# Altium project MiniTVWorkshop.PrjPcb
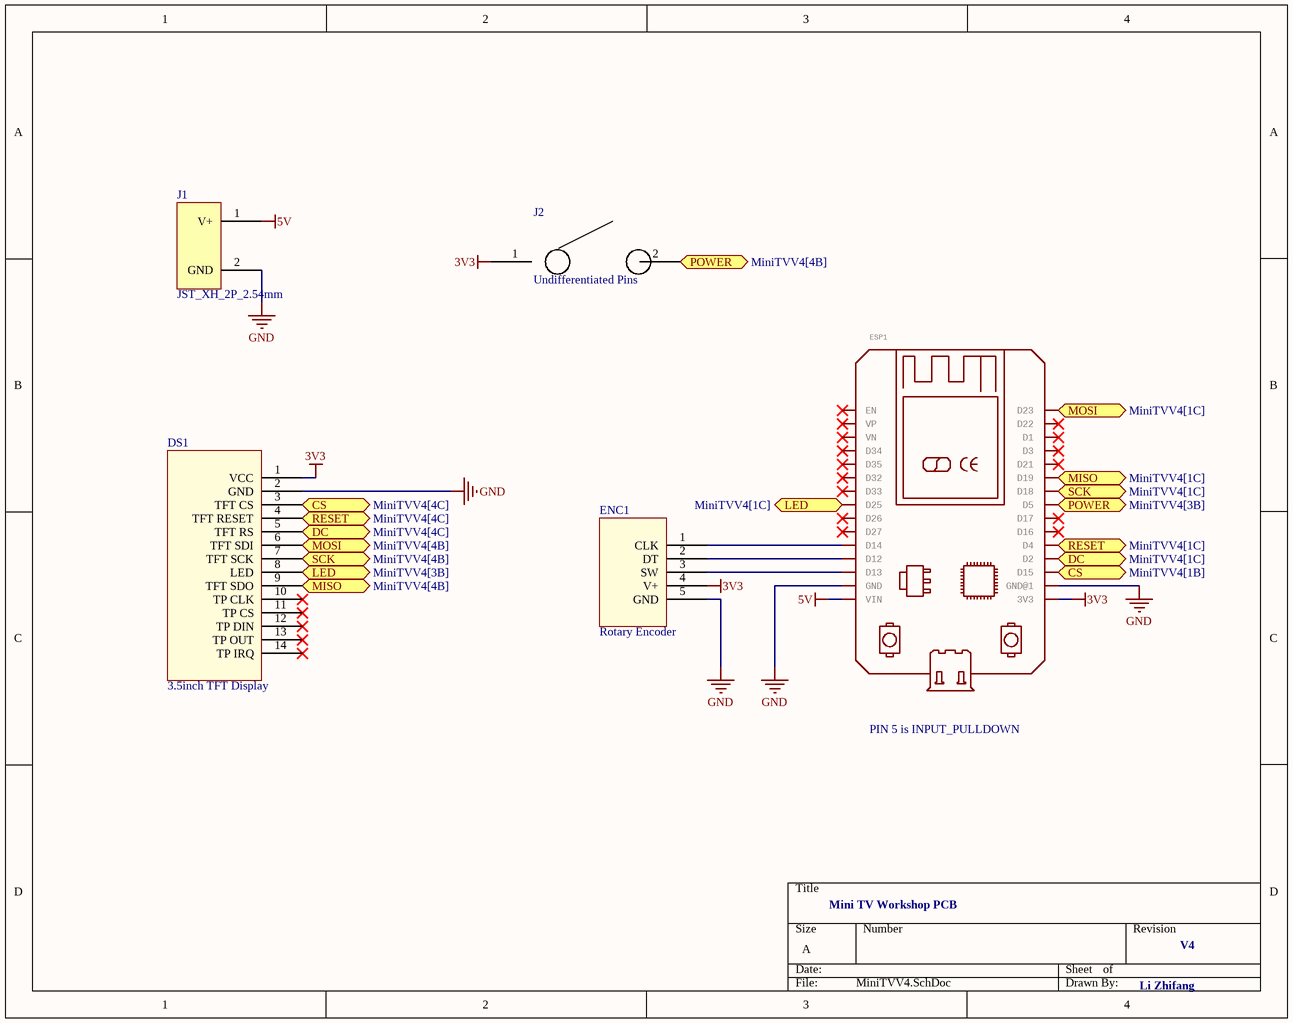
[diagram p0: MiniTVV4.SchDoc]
1 sheet, 5 parts. Net scope: flat (ports and power ports of the same name join across sheets).
Board file: MiniTVV4.PcbDoc

## Sheet MiniTVV4.SchDoc
size A; SheetNumber: 1; SheetTotal: 1

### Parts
DS1  3.5inch TFT Display  [3.5inch SPI Display]
ENC1  Rotary Encoder  [Rotary Encoder]
ESP1  https://github.com/shridattdudhat  [ESP32-DEVKITV1]  (value not drawn)
J1  JST_XH_2P_2.54mm  [JST_XH_2P_2.54mm]
J2  Undifferentiated Pins  [2-Pin 2.54mm]

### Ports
CS (bidir, see MiniTVV4[1B]), CS (bidir, see MiniTVV4[4C]), DC (bidir, see MiniTVV4[1C]), DC (bidir, see MiniTVV4[4C]), LED (bidir, see MiniTVV4[1C]), LED (bidir, see MiniTVV4[3B]), MISO (bidir, see MiniTVV4[1C]), MISO (bidir, see MiniTVV4[4B]), MOSI (bidir, see MiniTVV4[1C]), MOSI (bidir, see MiniTVV4[4B]), POWER (bidir, see MiniTVV4[3B]), POWER (bidir, see MiniTVV4[4B]), RESET (bidir, see MiniTVV4[1C]), RESET (bidir, see MiniTVV4[4C]), SCK (bidir, see MiniTVV4[1C]), SCK (bidir, see MiniTVV4[4B])

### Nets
3V3: DS1.1(VCC) ENC1.4(V+) ESP1.3V3 J2.1
5V: ESP1.VIN J1.1(V+)
GND: DS1.2(GND) ENC1.5(GND) ESP1.GND ESP1.GND@1 J1.2(GND)
NetDS1_3: DS1.3(TFT_CS) ESP1.D15 ; port CS
NetDS1_4: DS1.4(TFT_RESET) ESP1.D4 ; port RESET
NetDS1_5: DS1.5(TFT_RS) ESP1.D2 ; port DC
NetDS1_6: DS1.6(TFT_SDI) ESP1.D23 ; port MOSI
NetDS1_7: DS1.7(TFT_SCK) ESP1.D18 ; port SCK
NetDS1_8: DS1.8(LED) ESP1.D25 ; port LED
NetDS1_9: DS1.9(TFT_SDO) ESP1.D19 ; port MISO
NetENC1_1: ENC1.1(CLK) ESP1.D14
NetENC1_2: ENC1.2(DT) ESP1.D12
NetENC1_3: ENC1.3(SW) ESP1.D13
NetESP1_D5: ESP1.D5 J2.2 ; port POWER

Not connected (* = marked no-connect by the designer): DS1 10(TP_CLK)* 11(TP_CS)* 12(TP_DIN)* 13(TP_OUT)* 14(TP_IRQ)*; ESP1 D1* D3* D16* D17* D21* D22* D26* D27* D32* D33* D34* D35* EN* VN* VP*

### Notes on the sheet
- PIN 5 is INPUT_PULLDOWN
- Mini TV Workshop PCB
- Li Zhifang
- V4

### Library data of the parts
ESP1 = ESP32DEVKITV1: GateName_1: G$1
J2 = SPST 2-Pin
